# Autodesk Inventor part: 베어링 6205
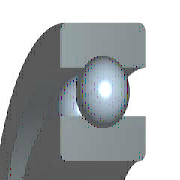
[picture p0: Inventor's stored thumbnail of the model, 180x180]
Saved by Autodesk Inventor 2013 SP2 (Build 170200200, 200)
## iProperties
IsCustomPart: 1
Company: 한국ATC센터
Created: 2014-10
Part Number: 베어링 6205
Material: 강, 연강
Description: 깊은 그루브 볼 베어링
Document SubType Name: Modeling
Standard: KS B 2023
Designer: 한국ATC센터
Standards Organization: KS
Language: ko-KR
Size Designation: 6205 - 25 x 52 x 15
Categories: <MemberInstance><Categories><Category DisplayName="샤프트 부품" InternalName="7f7aeb1f-a693-4053-b835-cee3144e0d98" Mnemonic="SHFT"><Category DisplayName="베어링" Inter
Density: 7.86 g/cm^3
Mass: 129.543 g
Surface Area: 107.326 cm^2
Volume: 16.4813 cm^3
Author: KYOUNG IL JANG
Revision Number: 1
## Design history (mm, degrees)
sketch "스케치" dims "d0" = 7.02 (= -0.26 x WD + 0.26 x BD)
  geometry: L1 (3.99, 19.25)-(11.01, 19.25); L2 (7.5, 19.25)-(7.5, 15.74); L3 (7.5, 19.25)-(7.5, 22.76); L4 (4.892, 16.901)-(0, 16.901); L5 (0, 12.5)-(15, 12.5); L6 (4.892, 21.599)-(0, 21.599); L7 (0, 26)-(15, 26); L8 (15, 12.5)-(15, 16.901); L9 (10.108, 16.901)-(15, 16.901); L10 (10.108, 21.599)-(15, 21.599); L11 (15, 26)-(15, 21.599); L12 (-1.4, 0)-(8.4, 0) reference; L13 (0, -0.3)-(0, 5.3) reference
  constraints: 22 end point, 4 point on line, 2 collinear, 2 perpendicular, 2 symmetric about line, 1 midpoint, 1 parallel, 14 other
  dimensions: "d9" = 25 diameter of L5 L12 (= WD); "d11" = 52 diameter of L7 L12 (= BD); "d12" = 15 distance between parallel lines of L8 L13 (= KB); "d13" = 33.802 diameter of L9 L12 (= 0.326 x BD + 0.674 x WD)
revolve "본체" stored, may be unused: angle "d6" = 90 deg
revolve "볼" stored, may be unused: angle "d7" = 90 deg
pattern_circular "IDS_ARRAYBALL[SIMPL:T]" dims angle "d3" = 360 deg
body "Solid1"
fillet "모깎기1" dims "d1" = 1 (= KRS)
other parameters: "WD" = 25 [user parameter; used in 5 equation terms], "BD" = 52 [user parameter; used in 5 equation terms], "KB" = 15 [user parameter; used in 1 equation term], "KRS" = 1 [user parameter; used in 1 equation term], "d4" = 0, "d5" = 0, "d8" = 0, "d14" = 0, "d15" = 0, "BBA" = 0 [user parameter], "BC0" = 7800000 [user parameter], "BC" = 1.4e+07 [user parameter], "BR" = 26 (= 0.5 x BD) [user parameter], "WR" = 12.5 (= 0.5 x WD) [user parameter]
